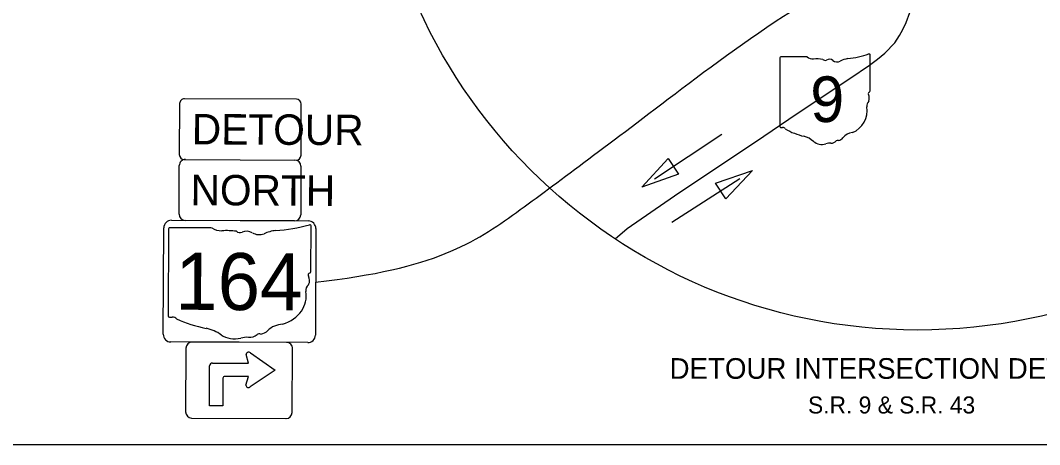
# Model space of a CAD drawing. Extents: x -202 to 1556, y 0 to 676.
# Drawn here: x 356.1 to 523.6, y 220 to 289.7 of the extents above; entities that cross this region are included whole.
import ezdxf

# ---------------------------------------------------------------- set-up
doc = ezdxf.new("R2010")
doc.units = 0
for name, color, linetype in [('Default', 7, 'Continuous'), ('GM_X_City_Street', 7, 'Continuous'), ('GM_X_Minor_Lake', 7, 'Continuous'), ('GM_X_Minor_River_Text', 7, 'Continuous'), ('SH_Data', 7, 'Continuous')]:
    doc.layers.add(name, color=color, linetype=linetype)

msp = doc.modelspace()

# ---------------------------------------------------------------- linework, layer by layer
at = {"layer": 'Default'}
for p, q in [((460.31, 263.68), (471.41, 271.02)), ((474.36, 263.72), (463.17, 256.53))]:
    msp.add_line(p, q, dxfattribs=at)
msp.add_lwpolyline([(453.85, 253.83), (455.86, 255.51), (463.64, 260.9), (478.31, 270.7), (483.79, 274.45), (492.41, 280.21), (495.65, 282.4), (496.96, 283.36), (498.18, 284.37), (499.83, 286.07), (500.62, 287.27), (501.16, 288.25), (501.69, 289.38), (502.3, 291.03), (502.57, 292.38), (502.68, 293.54), (502.8, 295.12), (502.92, 296.94), (502.99, 298.87), (502.99, 301.52), (503.08, 319.32), (503.18, 321.83), (503.59, 328.84)], dxfattribs=at)
for points in [[(464.29, 264.45), (458.23, 262.31), (462.57, 267.05)], [(470.37, 263.01), (476.46, 265.07), (472.06, 260.39)]]:
    msp.add_lwpolyline(points, close=True, dxfattribs=at)
at = {"layer": 'GM_X_City_Street'}
for p, q in [((480.93, 283.57), (480.93, 272.31)), ((485.42, 283.76), (481.07, 283.76)), ((495.76, 278.15), (495.76, 284.04)), ((495.76, 278.15), (495.76, 278.15))]:
    msp.add_line(p, q, dxfattribs=at)
for centre, radius, start, end in [((481.1, 283.59), 0.172, 98.1301, 188.1301), ((486.45, 285.07), 1.67, 231.6195, 271.1119), ((487, 277.44), 5.98, 80.4867, 94.9883), ((488.36, 283.65), 0.481, 219.7921, 297.1024), ((489.07, 282.35), 1, 54.4667, 119.1411), ((490.36, 284.13), 1.2, 233.8562, 294.8282), ((492.48, 280.32), 3.16, 97.3462, 120.7689), ((490.47, 299.11), 15.73, 275.8445, 288.9065), ((495.59, 284.06), 0.165, 351.8621, 97.738), ((495.58, 278.13), 0.177, 289.6038, 7.7341), ((496.35, 275.69), 1.12, 136.8065, 186.9296), ((495.72, 277.72), 0.256, 107.944, 210.337), ((494.09, 276.97), 1.53, 340.033, 23.6496), ((491.36, 274.94), 3.93, 292.3089, 8.9858), ((481.1, 272.29), 0.173, 171.9584, 258.3066), ((481.12, 273.44), 1.32, 267.339, 280.6039), ((481.4, 271.66), 0.477, 29.7484, 93.2717), ((487.42, 281.77), 11.36, 240.4129, 257.1985), ((484.03, 267.25), 3.55, 47.1842, 75.836), ((487.87, 271.61), 2.26, 230.7004, 286.2918), ((489.34, 270.76), 1.2, 268.777, 315.5493), ((490.43, 269.67), 0.338, 65.7517, 132.6484), ((490.28, 271.22), 1.27, 282.8732, 323.2771), ((493.01, 269.15), 2.15, 94.4031, 142.5768), ((489.18, 267.71), 1.85, 85.6951, 111.2099)]:
    msp.add_arc(centre, radius, start, end, dxfattribs=at)
at = {"layer": 'GM_X_Minor_Lake'}
for p, q in [((383.25, 266.87), (401.25, 266.78)), ((382.2, 257.88), (382.24, 265.88)), ((402.24, 265.77), (402.2, 257.77)), ((401.2, 256.78), (383.2, 256.87)), ((380.47, 255.41), (380.4, 241.18)), ((387.56, 255.62), (380.7, 255.66)), ((403.87, 248.45), (403.91, 255.89)), ((403.87, 248.45), (403.87, 248.45)), ((399.84, 236.79), (384.34, 236.87)), ((383.34, 235.87), (383.28, 225.37)), ((393.64, 233.38), (393.23, 234.79)), ((393.94, 235.08), (398.01, 232.26)), ((400.78, 225.28), (400.84, 235.78)), ((387.19, 226.38), (387.23, 232.94)), ((387.7, 233.41), (393.64, 233.38)), ((387.7, 233.41), (387.7, 233.41)), ((393.62, 231.19), (389.72, 231.21)), ((393.2, 229.79), (393.62, 231.19)), ((398.01, 232.26), (393.91, 229.49)), ((389.4, 230.9), (389.38, 226.37)), ((389.38, 226.37), (387.19, 226.38)), ((384.28, 224.37), (399.78, 224.29))]:
    msp.add_line(p, q, dxfattribs=at)
for points in [[(401.5, 276.78), (383.1, 276.87)], [(382.3, 276.08), (382.25, 267.68)], [(402.25, 267.57), (402.29, 275.97)], [(383.05, 266.87), (401.45, 266.78)], [(380.95, 256.88), (403.45, 256.77)], [(379.6, 238.14), (379.69, 255.64)], [(404.69, 255.51), (404.6, 238.01)], [(403.34, 236.77), (380.84, 236.88)]]:
    msp.add_lwpolyline(points, dxfattribs=at)
for centre, radius, start, end in [((383.1, 276.07), 0.8, 89.7036, 179.7036), ((401.49, 275.98), 0.8, 359.7036, 89.7036), ((383.24, 265.87), 1, 89.7036, 179.7036), ((383.05, 267.67), 0.8, 179.7036, 269.7036), ((401.24, 265.78), 1, 359.7036, 89.7036), ((401.45, 267.58), 0.8, 269.7036, 359.7036), ((380.94, 255.63), 1.25, 89.7036, 179.7036), ((383.2, 257.87), 1, 179.7036, 269.7036), ((401.2, 257.78), 1, 269.7036, 359.7036), ((403.44, 255.52), 1.25, 359.7036, 89.7036), ((380.85, 238.13), 1.25, 179.7036, 269.7036), ((403.35, 238.02), 1.25, 269.7036, 359.7036), ((384.34, 235.87), 1, 89.7043, 179.7043), ((399.84, 235.79), 1, 359.7043, 89.7043), ((393.64, 234.79), 0.417, 44.7045, 179.7027), ((387.7, 232.94), 0.469, 89.7043, 179.7043), ((389.72, 230.9), 0.312, 89.7043, 179.7043), ((393.62, 229.79), 0.417, 179.7027, 314.7042), ((384.28, 225.37), 1, 179.7043, 269.7043), ((399.78, 225.29), 1, 269.7043, 359.7043)]:
    msp.add_arc(centre, radius, start, end, dxfattribs=at)
for centre, major_axis, start_param, end_param in [((380.74, 255.44), (0.272, -0.001), 1.712693, 3.28349), ((389.21, 257.27), (2.63, -0.01), 4.042523, 4.731795), ((390.03, 247.62), (9.45, -0.05), 1.404758, 1.657858), ((392.22, 255.46), (0.76, -0.004), 3.836095, 5.185415), ((393.32, 253.81), (1.58, -0.01), 0.950623, 2.079405), ((395.38, 256.05), (1.9, -0.01), 4.081561, 5.145723), ((398.71, 251.22), (5, -0.03), 1.699011, 2.107814), ((395.66, 274.98), (24.85, -0.13), 4.814394, 5.042369), ((403.65, 255.92), (0.261, -0.001), 6.141152, 7.989035), ((403.81, 247.9), (0.404, -0.002), 1.883978, 3.671073), ((403.59, 248.42), (0.279, -0.001), 5.05454, 6.418171), ((404.79, 245.33), (1.76, -0.01), 2.387724, 3.262537), ((401.23, 246.97), (2.42, -0.01), 5.934695, 6.695948), ((396.89, 244.42), (6.22, -0.03), 5.101752, 6.440018), ((380.67, 241.15), (0.274, -0.001), 3.00124, 4.508301), ((380.72, 242.61), (2.09, -0.01), 4.665946, 4.897461), ((381.13, 240.36), (0.754, -0.004), 0.519207, 1.627899), ((390.71, 253.1), (17.95, -0.09), 4.195997, 4.488961), ((399.48, 237.09), (3.4, -0.02), 1.647645, 2.488434), ((385.27, 234.77), (5.62, -0.03), 0.823519, 1.323587), ((391.37, 240.24), (3.56, -0.02), 4.026481, 4.996735), ((393.68, 239.16), (1.9, -0.01), 4.691044, 5.507374), ((395.39, 237.77), (0.535, -0.003), 1.147584, 2.315152), ((395.18, 239.73), (2.01, -0.01), 4.937069, 5.64225), ((393.4, 235.3), (2.93, -0.02), 1.495662, 1.94098)]:
    msp.add_ellipse(centre, major_axis=major_axis, ratio=0.8, start_param=start_param, end_param=end_param, dxfattribs=at)
at = {"layer": 'GM_X_Minor_River_Text'}
msp.add_line((30, 220), (640, 220), dxfattribs=at)
at = {"layer": 'SH_Data'}
msp.add_circle((503.59, 328.84), 90, dxfattribs=at)
msp.add_open_spline([(404.64, 246.73), (424.34, 248.87), (437.23, 257.61), (458.97, 274.11), (492.42, 299.36), (506.59, 301.5)], degree=3, dxfattribs=at)

# ---------------------------------------------------------------- texts
at = {"layer": 'GM_X_City_Street'}
msp.add_text('9', height=7.5, dxfattribs=at).set_placement((485.93, 273.04))
at = {"layer": 'GM_X_Minor_Lake'}
for s, height, p in [('DETOUR', 5, (384.29, 269.37)), ('NORTH', 5, (384.08, 259.37)), ('164', 9.375, (381.55, 242.18))]:
    msp.add_text(s, height=height, rotation=359.7036, dxfattribs=at).set_placement(p)
at = {"layer": 'GM_X_Minor_River_Text'}
for s, height, p in [('DETOUR INTERSECTION DETAIL 2', 3.4, (462.81, 230.82)), ('S.R. 9 & S.R. 43', 2.8, (485.56, 225.12))]:
    msp.add_text(s, height=height, dxfattribs=at).set_placement(p)

doc.saveas('drawing.dxf')
